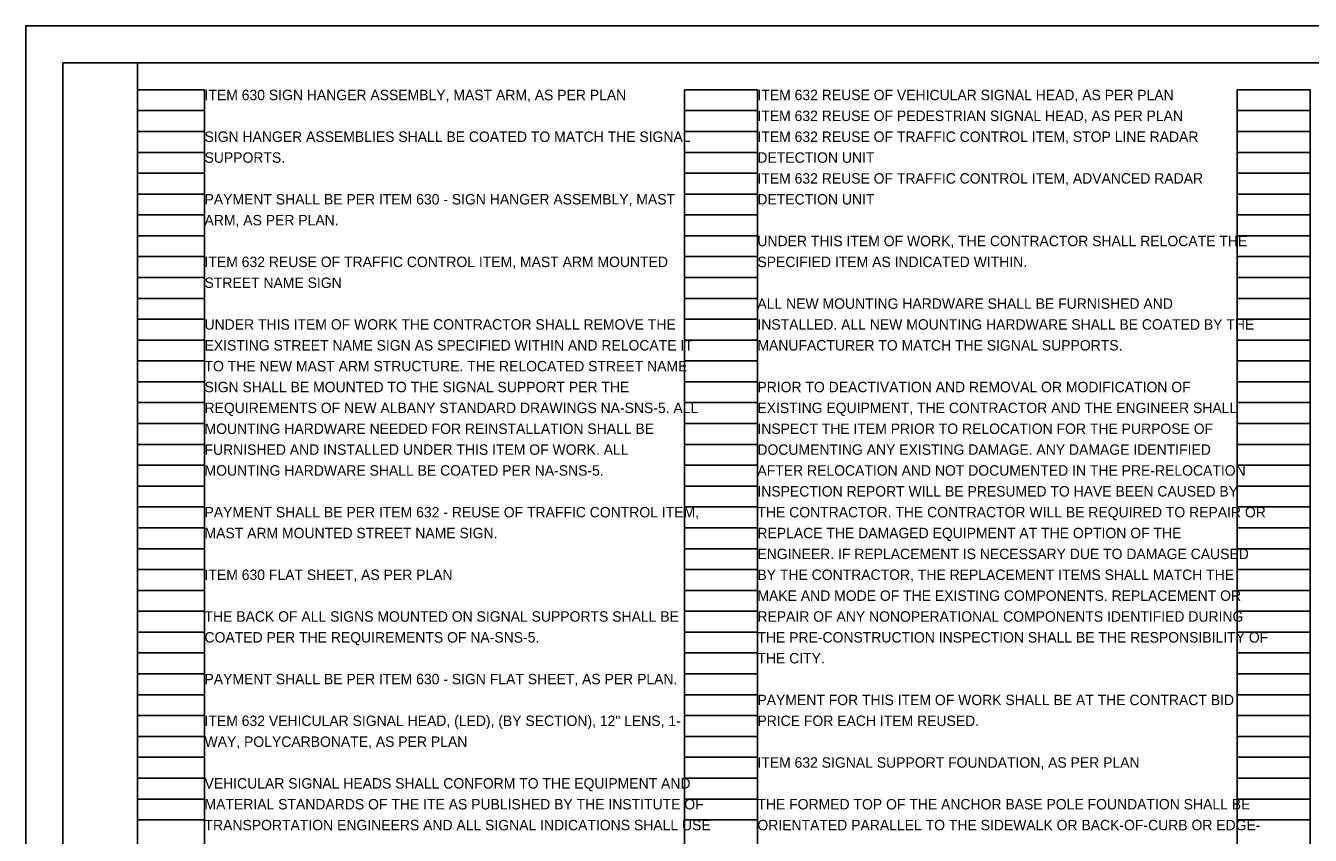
# Model space of a CAD drawing. Extents: x 0 to 34, y 0 to 22.
# Drawn here: x 0 to 17.24, y 11.13 to 22 of the extents above; entities that cross this region are included whole.
import ezdxf

# ---------------------------------------------------------------- set-up
doc = ezdxf.new("R2010")
doc.units = 0
for name, color, linetype in [('SH_Border', 7, 'Continuous'), ('SH_Cut_Line', 7, 'Continuous'), ('SH_Data', 7, 'Continuous'), ('SH_Text', 7, 'Continuous')]:
    doc.layers.add(name, color=color, linetype=linetype)

msp = doc.modelspace()

# ---------------------------------------------------------------- linework, layer by layer
at = {"layer": 'SH_Border'}
for points in [[(0.5, 21.5), (1.5, 21.5), (1.5, 0.5), (0.5, 0.5)], [(1.5, 21.5), (33.5, 21.5), (33.5, 0.5), (1.5, 0.5)]]:
    msp.add_lwpolyline(points, close=True, dxfattribs=at)
at = {"layer": 'SH_Cut_Line'}
msp.add_lwpolyline([(0, 0), (34, 0), (34, 22), (0, 22)], close=True, dxfattribs=at)
at = {"layer": 'SH_Data'}
for p, q in [((1.5, 0.98), (1.5, 21.14)), ((1.5, 21.14), (2.4, 21.14)), ((2.4, 0.98), (2.4, 21.14)), ((8.84, 0.98), (8.84, 21.14)), ((8.84, 21.14), (9.82, 21.14)), ((9.82, 0.98), (9.82, 21.14)), ((16.26, 0.98), (16.26, 21.14)), ((16.26, 21.14), (17.24, 21.14)), ((17.24, 0.98), (17.24, 21.14)), ((1.5, 20.86), (2.4, 20.86)), ((8.84, 20.86), (9.82, 20.86)), ((16.26, 20.86), (17.24, 20.86)), ((1.5, 20.58), (2.4, 20.58)), ((8.84, 20.58), (9.82, 20.58)), ((16.26, 20.58), (17.24, 20.58)), ((1.5, 20.3), (2.4, 20.3)), ((8.84, 20.3), (9.82, 20.3)), ((16.26, 20.3), (17.24, 20.3)), ((1.5, 20.02), (2.4, 20.02)), ((8.84, 20.02), (9.82, 20.02)), ((16.26, 20.02), (17.24, 20.02)), ((1.5, 19.74), (2.4, 19.74)), ((8.84, 19.74), (9.82, 19.74)), ((16.26, 19.74), (17.24, 19.74)), ((1.5, 19.46), (2.4, 19.46)), ((8.84, 19.46), (9.82, 19.46)), ((16.26, 19.46), (17.24, 19.46)), ((1.5, 19.18), (2.4, 19.18)), ((8.84, 19.18), (9.82, 19.18)), ((16.26, 19.18), (17.24, 19.18)), ((1.5, 18.9), (2.4, 18.9)), ((8.84, 18.9), (9.82, 18.9)), ((16.26, 18.9), (17.24, 18.9)), ((1.5, 18.62), (2.4, 18.62)), ((8.84, 18.62), (9.82, 18.62)), ((16.26, 18.62), (17.24, 18.62)), ((1.5, 18.34), (2.4, 18.34)), ((8.84, 18.34), (9.82, 18.34)), ((16.26, 18.34), (17.24, 18.34)), ((1.5, 18.06), (2.4, 18.06)), ((8.84, 18.06), (9.82, 18.06)), ((16.26, 18.06), (17.24, 18.06)), ((1.5, 17.78), (2.4, 17.78)), ((8.84, 17.78), (9.82, 17.78)), ((16.26, 17.78), (17.24, 17.78)), ((1.5, 17.5), (2.4, 17.5)), ((8.84, 17.5), (9.82, 17.5)), ((16.26, 17.5), (17.24, 17.5)), ((1.5, 17.22), (2.4, 17.22)), ((8.84, 17.22), (9.82, 17.22)), ((16.26, 17.22), (17.24, 17.22)), ((1.5, 16.94), (2.4, 16.94)), ((8.84, 16.94), (9.82, 16.94)), ((16.26, 16.94), (17.24, 16.94)), ((1.5, 16.66), (2.4, 16.66)), ((8.84, 16.66), (9.82, 16.66)), ((16.26, 16.66), (17.24, 16.66)), ((1.5, 16.38), (2.4, 16.38)), ((8.84, 16.38), (9.82, 16.38)), ((16.26, 16.38), (17.24, 16.38)), ((1.5, 16.1), (2.4, 16.1)), ((8.84, 16.1), (9.82, 16.1)), ((16.26, 16.1), (17.24, 16.1)), ((1.5, 15.82), (2.4, 15.82)), ((8.84, 15.82), (9.82, 15.82)), ((16.26, 15.82), (17.24, 15.82)), ((1.5, 15.54), (2.4, 15.54)), ((8.84, 15.54), (9.82, 15.54)), ((16.26, 15.54), (17.24, 15.54)), ((1.5, 15.26), (2.4, 15.26)), ((8.84, 15.26), (9.82, 15.26)), ((16.26, 15.26), (17.24, 15.26)), ((1.5, 14.98), (2.4, 14.98)), ((8.84, 14.98), (9.82, 14.98)), ((16.26, 14.98), (17.24, 14.98)), ((1.5, 14.7), (2.4, 14.7)), ((8.84, 14.7), (9.82, 14.7)), ((16.26, 14.7), (17.24, 14.7)), ((1.5, 14.42), (2.4, 14.42)), ((8.84, 14.42), (9.82, 14.42)), ((16.26, 14.42), (17.24, 14.42)), ((1.5, 14.14), (2.4, 14.14)), ((8.84, 14.14), (9.82, 14.14)), ((16.26, 14.14), (17.24, 14.14)), ((1.5, 13.86), (2.4, 13.86)), ((8.84, 13.86), (9.82, 13.86)), ((16.26, 13.86), (17.24, 13.86)), ((1.5, 13.58), (2.4, 13.58)), ((8.84, 13.58), (9.82, 13.58)), ((16.26, 13.58), (17.24, 13.58)), ((1.5, 13.3), (2.4, 13.3)), ((8.84, 13.3), (9.82, 13.3)), ((16.26, 13.3), (17.24, 13.3)), ((1.5, 13.02), (2.4, 13.02)), ((8.84, 13.02), (9.82, 13.02)), ((16.26, 13.02), (17.24, 13.02)), ((1.5, 12.74), (2.4, 12.74)), ((8.84, 12.74), (9.82, 12.74)), ((16.26, 12.74), (17.24, 12.74)), ((1.5, 12.46), (2.4, 12.46)), ((8.84, 12.46), (9.82, 12.46)), ((16.26, 12.46), (17.24, 12.46)), ((1.5, 12.18), (2.4, 12.18)), ((8.84, 12.18), (9.82, 12.18)), ((16.26, 12.18), (17.24, 12.18)), ((1.5, 11.9), (2.4, 11.9)), ((8.84, 11.9), (9.82, 11.9)), ((16.26, 11.9), (17.24, 11.9)), ((1.5, 11.62), (2.4, 11.62)), ((8.84, 11.62), (9.82, 11.62)), ((16.26, 11.62), (17.24, 11.62)), ((1.5, 11.34), (2.4, 11.34)), ((8.84, 11.34), (9.82, 11.34)), ((16.26, 11.34), (17.24, 11.34))]:
    msp.add_line(p, q, dxfattribs=at)

# ---------------------------------------------------------------- texts
at = {"layer": 'SH_Text'}
for s, p in [('ITEM 630 SIGN HANGER ASSEMBLY, MAST ARM, AS PER PLAN', (2.4, 21)), ('ITEM 632 REUSE OF VEHICULAR SIGNAL HEAD, AS PER PLAN', (9.82, 21)), ('ITEM 632 REUSE OF PEDESTRIAN SIGNAL HEAD, AS PER PLAN', (9.82, 20.72)), ('SIGN HANGER ASSEMBLIES SHALL BE COATED TO MATCH THE SIGNAL ', (2.4, 20.44)), ('ITEM 632 REUSE OF TRAFFIC CONTROL ITEM, STOP LINE RADAR ', (9.82, 20.44)), ('SUPPORTS.', (2.4, 20.16)), ('DETECTION UNIT', (9.82, 20.16)), ('ITEM 632 REUSE OF TRAFFIC CONTROL ITEM, ADVANCED RADAR ', (9.82, 19.88)), ('PAYMENT SHALL BE PER ITEM 630 - SIGN HANGER ASSEMBLY, MAST ', (2.4, 19.6)), ('DETECTION UNIT', (9.82, 19.6)), ('ARM, AS PER PLAN.', (2.4, 19.32)), ('UNDER THIS ITEM OF WORK, THE CONTRACTOR SHALL RELOCATE THE ', (9.82, 19.04)), ('ITEM 632 REUSE OF TRAFFIC CONTROL ITEM, MAST ARM MOUNTED ', (2.4, 18.76)), ('SPECIFIED ITEM AS INDICATED WITHIN.', (9.82, 18.76)), ('STREET NAME SIGN', (2.4, 18.48)), ('ALL NEW MOUNTING HARDWARE SHALL BE FURNISHED AND ', (9.82, 18.2)), ('UNDER THIS ITEM OF WORK THE CONTRACTOR SHALL REMOVE THE ', (2.4, 17.92)), ('INSTALLED. ALL NEW MOUNTING HARDWARE SHALL BE COATED BY THE ', (9.82, 17.92)), ('EXISTING STREET NAME SIGN AS SPECIFIED WITHIN AND RELOCATE IT ', (2.4, 17.64)), ('MANUFACTURER TO MATCH THE SIGNAL SUPPORTS.', (9.82, 17.64)), ('TO THE NEW MAST ARM STRUCTURE. THE RELOCATED STREET NAME ', (2.4, 17.36)), ('SIGN SHALL BE MOUNTED TO THE SIGNAL SUPPORT PER THE ', (2.4, 17.08)), ('PRIOR TO DEACTIVATION AND REMOVAL OR MODIFICATION OF ', (9.82, 17.08)), ('REQUIREMENTS OF NEW ALBANY STANDARD DRAWINGS NA-SNS-5. ALL ', (2.4, 16.8)), ('EXISTING EQUIPMENT, THE CONTRACTOR AND THE ENGINEER SHALL ', (9.82, 16.8)), ('MOUNTING HARDWARE NEEDED FOR REINSTALLATION SHALL BE ', (2.4, 16.52)), ('INSPECT THE ITEM PRIOR TO RELOCATION FOR THE PURPOSE OF ', (9.82, 16.52)), ('FURNISHED AND INSTALLED UNDER THIS ITEM OF WORK. ALL ', (2.4, 16.24)), ('DOCUMENTING ANY EXISTING DAMAGE. ANY DAMAGE IDENTIFIED ', (9.82, 16.24)), ('MOUNTING HARDWARE SHALL BE COATED PER NA-SNS-5.', (2.4, 15.96)), ('AFTER RELOCATION AND NOT DOCUMENTED IN THE PRE-RELOCATION ', (9.82, 15.96)), ('INSPECTION REPORT WILL BE PRESUMED TO HAVE BEEN CAUSED BY ', (9.82, 15.68)), ('PAYMENT SHALL BE PER ITEM 632 - REUSE OF TRAFFIC CONTROL ITEM, ', (2.4, 15.4)), ('THE CONTRACTOR. THE CONTRACTOR WILL BE REQUIRED TO REPAIR OR ', (9.82, 15.4)), ('MAST ARM MOUNTED STREET NAME SIGN.', (2.4, 15.12)), ('REPLACE THE DAMAGED EQUIPMENT AT THE OPTION OF THE ', (9.82, 15.12)), ('ENGINEER. IF REPLACEMENT IS NECESSARY DUE TO DAMAGE CAUSED ', (9.82, 14.84)), ('ITEM 630 FLAT SHEET, AS PER PLAN', (2.4, 14.56)), ('BY THE CONTRACTOR, THE REPLACEMENT ITEMS SHALL MATCH THE ', (9.82, 14.56)), ('MAKE AND MODE OF THE EXISTING COMPONENTS. REPLACEMENT OR ', (9.82, 14.28)), ('THE BACK OF ALL SIGNS MOUNTED ON SIGNAL SUPPORTS SHALL BE ', (2.4, 14)), ('REPAIR OF ANY NONOPERATIONAL COMPONENTS IDENTIFIED DURING ', (9.82, 14)), ('COATED PER THE REQUIREMENTS OF NA-SNS-5.', (2.4, 13.72)), ('THE PRE-CONSTRUCTION INSPECTION SHALL BE THE RESPONSIBILITY OF ', (9.82, 13.72)), ('THE CITY.', (9.82, 13.44)), ('PAYMENT SHALL BE PER ITEM 630 - SIGN FLAT SHEET, AS PER PLAN.', (2.4, 13.16)), ('PAYMENT FOR THIS ITEM OF WORK SHALL BE AT THE CONTRACT BID ', (9.82, 12.88)), ('ITEM 632 VEHICULAR SIGNAL HEAD, (LED), (BY SECTION), 12" LENS, 1-', (2.4, 12.6)), ('PRICE FOR EACH ITEM REUSED.', (9.82, 12.6)), ('WAY, POLYCARBONATE, AS PER PLAN', (2.4, 12.32)), ('ITEM 632 SIGNAL SUPPORT FOUNDATION, AS PER PLAN', (9.82, 12.04)), ('VEHICULAR SIGNAL HEADS SHALL CONFORM TO THE EQUIPMENT AND ', (2.4, 11.76)), ('MATERIAL STANDARDS OF THE ITE AS PUBLISHED BY THE INSTITUTE OF ', (2.4, 11.48)), ('THE FORMED TOP OF THE ANCHOR BASE POLE FOUNDATION SHALL BE ', (9.82, 11.48)), ('TRANSPORTATION ENGINEERS AND ALL SIGNAL INDICATIONS SHALL USE ', (2.4, 11.2)), ('ORIENTATED PARALLEL TO THE SIDEWALK OR BACK-OF-CURB OR EDGE-', (9.82, 11.2))]:
    msp.add_text(s, height=0.14, dxfattribs=at).set_placement(p)

doc.saveas('drawing.dxf')
